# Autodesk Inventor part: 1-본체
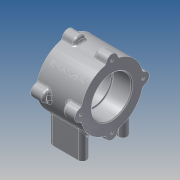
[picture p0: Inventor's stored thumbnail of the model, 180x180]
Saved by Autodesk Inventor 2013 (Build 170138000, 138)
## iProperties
Created: 2015-03
Part Number: 1-본체
Material: 알루미늄 6061
Document SubType Name: Modeling
Designer: kb
Density: 2.71 g/cm^3
Mass: 450.777 g
Surface Area: 332.735 cm^2
Volume: 166.339 cm^3
Author: kb
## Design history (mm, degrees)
sketch "스케치1"
  geometry: L1 (-26, 37)-(26, 37); L2 (26, 37)-(26, 23.5); L3 (26, 23.5)-(4, 23.5); L4 (4, 23.5)-(4, 21); L5 (4, 21)-(-4, 21); L6 (-4, 21)-(-4, 23.5); L7 (-4, 23.5)-(-26, 23.5); L8 (-26, 23.5)-(-26, 37); L9 (-26, 0)-(26, 0); 2 further points
  constraints: 18 end point, 5 parallel, 3 perpendicular, 2 vertical alignment, 1 coincident, 1 horizontal, 1 midpoint
  dimensions: "d1" = 47 diameter of L7 L9; "d3" = 42 diameter of L5 L9; "d4" = 47 diameter of L3 L9; "d5" = 74 diameter of L1 L9; "d6" = 52 distance of L1.start L1.end; "d7" = 22 distance of L6.end L7.end; "d8" = 22 distance of L2.end L3.end
revolve "회전1" sketch "스케치1" stored, may be unused: angle "d9" = 90 deg
sketch "스케치2"
  geometry: L1 (0, 37)-(0, 0); C1 r 23.5 at (0, 0) reference; A1 r 37 centre (0, 0) between (0, 37) and (6.969, 36.338) reference; A2 r 7 centre (0, 37) between (6.969, 36.338) and (-6.969, 36.338); 1 further point
  constraints: 5 point on circle, 2 coincident, 2 end point, 1 centre point, 1 vertical
  dimensions: "d10" = 14 diameter of A2
extrude "돌출1" join sketch "스케치2" distance "d11" = 15; taper "d12" = 0 deg
hole "구멍1" sketch "스케치2" diameter "d13" = 3.242; stored, may be unused: countersink angle "d17" = 90 deg, drill point angle "d19" = 118 deg; dims "d14" = 8, "d15" = 4, "d16" = 2, "d18" = 11
node "작업 평면1"
node "작업 평면2"
sketch "스케치3"
  geometry: L1 (15, -24)-(-15, -24); L2 (-15, -24)-(-15, 24); L3 (-15, 24)-(15, 24); L4 (15, 24)-(15, -24); L5 (15, -24)-(-15, 24); L6 (-15, -24)-(15, 24); L7 (15, 29)-(-15, 29); L8 (15, 19)-(-15, 19); L9 (15, -19)-(-15, -19); L10 (15, -29)-(-15, -29); A1 r 5 centre (-15, 24) between (-15, 29) and (-15, 19); A2 r 5 centre (15, 24) between (15, 29) and (15, 19); A3 r 5 centre (-15, -24) between (-15, -19) and (-15, -29); A4 r 5 centre (15, -24) between (15, -19) and (15, -29); 1 further point
  constraints: 20 end point, 8 point on circle, 5 tangent, 4 centre point, 4 coincident, 3 point on line, 2 midpoint, 2 parallel, 1 horizontal, 1 perpendicular
  dimensions: "d24" = 48 distance of L3.end L1.start; "d26" = 30 distance of L2.end L3.end; "d27" = 10 diameter of A1; "d28" = 10 diameter of A2; "d29" = 10 diameter of A3; "d30" = 10 diameter of A4
extrude "돌출2" join sketch "스케치3" stored distance "d31" = 15; taper "d32" = 0 deg
sketch "스케치4"
  geometry: L1 (0, -37)-(-37, -37); L2 (0, -37)-(-48.443, -85.443); A1 r 37 centre (0, -37) between (-36.338, -43.969) and (-6.969, -73.338) reference; A2 r 37 centre (0, -37) between (36.338, -30.031) and (6.969, -0.662) reference; A3 r 37 centre (0, -37) between (-36.338, -30.031) and (-36.338, -43.969) reference; 1 further point
  constraints: 4 end point, 1 horizontal, 1 point on circle
  dimensions: "d33" = 45 deg angle of L1 L2
node "작업 평면3"
sketch "스케치5"
  geometry: L1 (-26, 20.767)-(-26, -20.767) reference; 3 further points
  constraints: 1 coincident, 1 other
  dimensions: "d34" = 26 distance from line of point (0, 0) L1
feature "엠보싱1" sketch "스케치5" dims "d15" = 4, "d35" = 0.5, "d36" = 0
sketch "스케치6"
  geometry: L1 (15, -29)-(-15, -29) reference; L2 (-15, -19)-(15, -19) reference; A1 r 5 centre (-15, 24) between (-15, 29) and (-15, 19) reference; A2 r 5 centre (15, 24) between (15, 19) and (15, 29) reference; A3 r 5 centre (-15, -24) between (-15, -19) and (-15, -29) reference; A4 r 5 centre (15, -24) between (15, -29) and (15, -19) reference; 5 further points
  constraints: 4 coincident
hole "구멍2" sketch "스케치6" at (-15, 24), (15, 24), (-15, -24), (15, -24) diameter "d37" = 4.134; stored, may be unused: countersink angle "d41" = 90 deg, drill point angle "d43" = 118 deg; dims "d38" = 6, "d39" = 4, "d40" = 2, "d42" = 8
fillet "모깎기1" dims "d44" = 3
fillet "모깎기2" dims "d45" = 3, "d46" = 0.3
chamfer "모따기1" distance "d47" = 1; stored, may be unused: second distance "d48" = 2, angle "d49" = 45 deg
node "솔리드1"
pattern_circular "원형 패턴1" dims angle "d21" = 360 deg
mirror "대칭1"
other parameters: "d23" = -56
